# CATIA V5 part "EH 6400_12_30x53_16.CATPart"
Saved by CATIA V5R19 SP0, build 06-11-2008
Definition: EH 6400_12_30x53_16
Nomenclature: EH 6400_12_30x53_16
Description: PART--DESC
Material "Steel": density 7860 kg/m3, Young's modulus 2e+11 Pa, Poisson ratio 0.266, thermal expansion 1.17e-05 1/K
Bounding box of the stored display mesh (mm): x -19.55 to 19.55, y -19.55 to 19.55, z 77 to 142
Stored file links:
  G:\UTB\Kombinované\Bakalářská práce\Catia\FORMA\EH 6400_12_30x53_16.CATPart
  D:\Aplikace\CATIA\Nová složka\win_b64\startup\materials\Catalog.CATMaterial
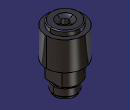
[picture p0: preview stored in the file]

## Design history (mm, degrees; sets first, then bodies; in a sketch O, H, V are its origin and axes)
Body1 "EH 6400_12_30x53_16" (main body)
  Solid1: solid without history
